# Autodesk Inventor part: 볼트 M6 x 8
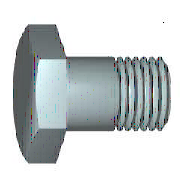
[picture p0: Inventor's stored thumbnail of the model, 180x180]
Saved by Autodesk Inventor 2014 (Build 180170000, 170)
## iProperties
Created: 2012-02
Part Number: 볼트 M6 x 8
Material: 강철, 연강
Description: 6각 머리 볼트 및 6각 머리 나사
Document SubType Name: Modeling
Standard: KS B 1002
Designer: mduedu
Standards Organization: KS
Language: ko-KR
Size Designation: C  M 6 x 12
Categories: <MemberInstance><Categories><Category DisplayName="조임쇠" InternalName="e4da775c-781d-43d5-af7c-5136215cf5a6" Mnemonic="FSTN"><Category DisplayName="볼트" InternalN
Density: 7.86 g/cm^3
Mass: 4.46616 g
Surface Area: 4.51243 cm^2
Volume: 0.568214 cm^3
Appearance: 강철
IsCustomPart: 1
Author: mduedu
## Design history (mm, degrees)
sketch "스케치1"
  geometry: L1 (0, 3)-(8, 3); L2 (8, 3)-(8, 0); L3 (8, 0)-(0, 0); L4 (-2.4, 0)-(14.4, 0) reference; L5 (0, -0.6)-(0, 3.6) reference; L6 (0, 3)-(0, 0)
  constraints: 8 end point, 3 point on line, 1 collinear
  dimensions: "d2" = 6 diameter of L1 L3 (= GD); "d59" = 8 distance between parallel lines of L2 L5 (= NLG)
revolve "본체" sketch "스케치1" stored, may be unused: angle "d12" = 90 deg
sketch "스케치2"
  geometry: L1 (0, 5.774)-(5, 2.887); L2 (5, 2.887)-(5, -2.887); L3 (5, -2.887)-(0, -5.774); L4 (0, -5.774)-(-5, -2.887); L5 (-5, -2.887)-(-5, 2.887); L6 (-5, 2.887)-(0, 5.774); L7 (-7, 0)-(7, 0) reference; L8 (0, 8.083)-(0, -8.083) reference; 2 further points
  constraints: 12 end point, 2 midpoint, 1 coincident, 1 vertical, 11 other
  dimensions: "d11" = 10 distance between parallel lines of L5 L2 (= SW)
extrude "머리" join sketch "스케치2" distance "d3" = 4 (= KOH); taper "d4" = 0 deg
revolve "모따기1" stored, may be unused: angle "d21" = 90 deg
workplane "Work Plane1"
body "Solid1"
feature "스레드" dims "d15" = 9 (= GEL), "d16" = 0
chamfer "모따기2" distance "d6" = 0.61345 (= -0.5 x SPD + 0.5 x GD); stored, may be unused: second distance "d7" = 0.61355 (computed from GUL), angle "d55" = 45 deg
sketch "스케치4"
  geometry: L1 (-3.423, 6)-(-4, 5); L2 (-1.1, 0)-(-0.234, 0); L3 (-4.753, 0)-(0.519, 0) reference; L4 (-4, 6)-(-3.423, 6); L5 (-4, 5)-(-4, 6); L6 (0, 7.2)-(0, -1.2) reference
  constraints: 8 end point, 1 parallel, 1 perpendicular, 1 point on line
  dimensions: "d65" = 10 diameter of L1.end L2 (= SW); "d67" = 30 deg angle of L1 L5 (= ANG1); "d68" = 12 diameter of L4 L2 (= 1.2 x SW); "d69" = 4 distance between parallel lines of L5 L6 (= KOH)
other parameters: "NLG" = 8 [user parameter; used in 1 equation term], "GD" = 6 (= NND) [user parameter; used in 2 equation terms], "BDM" = 6 (= NND) [user parameter], "KOH" = 4 [user parameter; used in 2 equation terms], "GEL" = 9 [user parameter; used in 1 equation term], "SW" = 10 [user parameter; used in 5 equation terms], "SPD" = 4.7731 (= NND - 1.2269 x PTC) [user parameter; used in 1 equation term], "SD2" = 6 (= NND) [user parameter], "SD" = 0 [user parameter], "ANG1" = 30 deg [user parameter; used in 1 equation term], "GAL" = 0.61345 (= 0.61345 x PTC) [user parameter], "GUL" = 0.61345 (= 0.61345 x PTC) [user parameter; used in 1 equation term], "d8" = 0, "RR" = 0.25 [user parameter], "d58" = 0, "RR1" = 0.1 [user parameter], "GD1" = 4.7731 (= THREADDIA - 1.2269 x PTC) [user parameter], "THREADDIA" = 6 [user parameter; used in 1 equation term], "TOA" = 30 deg [user parameter], "PTC" = 1 [user parameter; used in 5 equation terms], "NND" = 6 [user parameter; used in 4 equation terms], "E0" = 11.55 (= 1.155 x SW) [user parameter]
